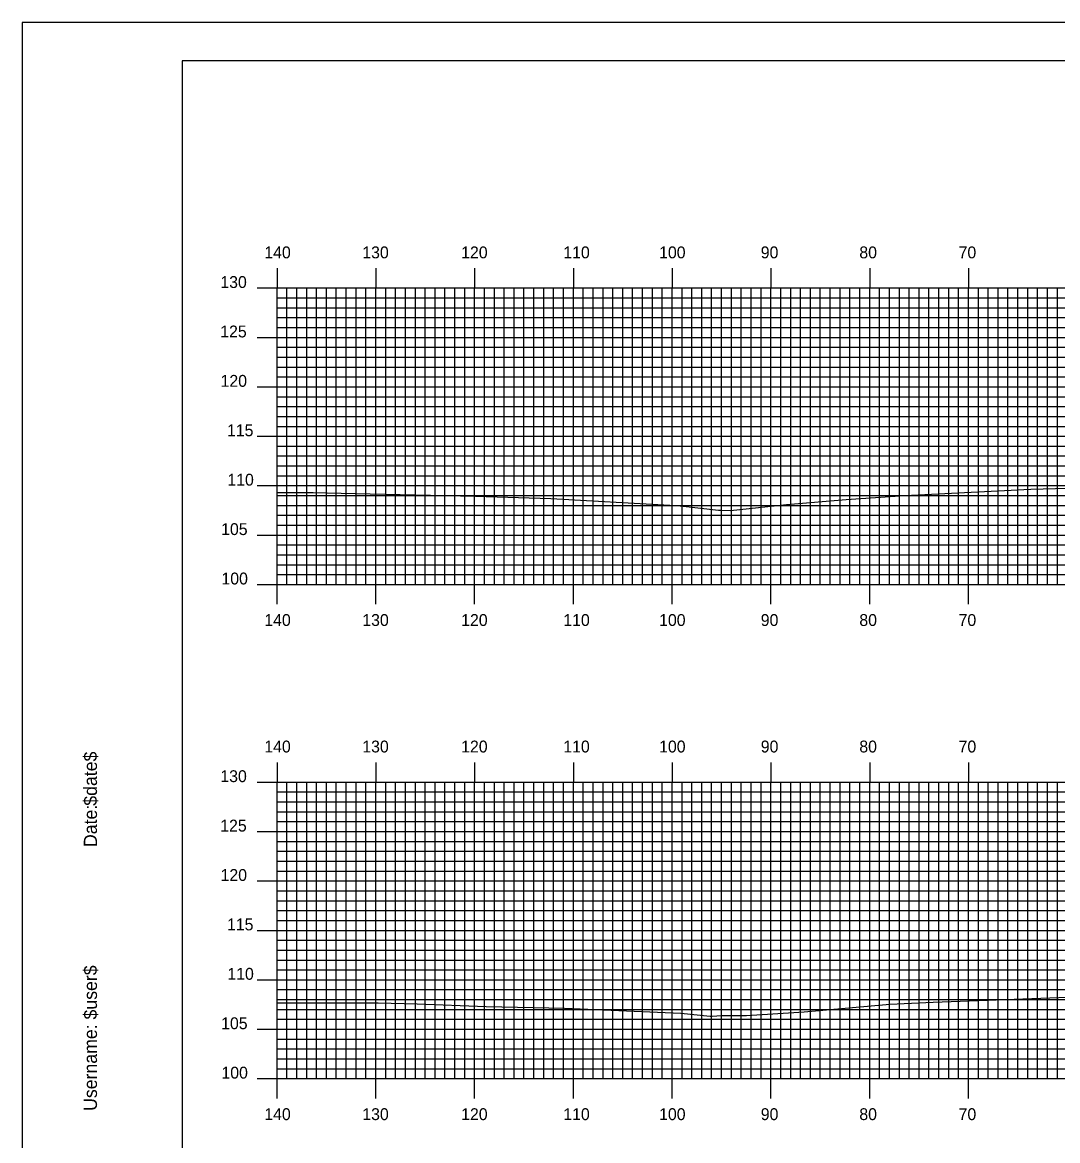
# Model space of a CAD drawing. Extents: x 1788156 to 1788500, y 442591 to 442811.
# Drawn here: x 1788156.3 to 1788261.2, y 442697.4 to 442810.5 of the extents above; entities that cross this region are included whole.
import ezdxf

# ---------------------------------------------------------------- set-up
doc = ezdxf.new("R2010")
doc.units = 0
for name, color, linetype in [('BORDER', 7, 'Continuous'), ('H_V ANNOTATION', 7, 'Continuous'), ('MAJOR', 7, 'Continuous'), ('MINOR', 7, 'Continuous'), ('PLOT BOUNDARY', 7, 'Continuous'), ('S_Roadway_Centerline', 7, 'Continuous')]:
    doc.layers.add(name, color=color, linetype=linetype)

msp = doc.modelspace()

# ---------------------------------------------------------------- linework, layer by layer
at = {"layer": 'BORDER'}
msp.add_lwpolyline([(1788172.53, 442596.67), (1788492.53, 442596.67), (1788492.53, 442806.67), (1788172.53, 442806.67)], close=True, dxfattribs=at)
at = {"layer": 'MAJOR'}
for p, q in [((1788182.13, 442785.67), (1788182.13, 442783.67)), ((1788192.13, 442785.67), (1788192.13, 442783.67)), ((1788202.13, 442785.67), (1788202.13, 442783.67)), ((1788212.13, 442785.67), (1788212.13, 442783.67)), ((1788222.13, 442785.67), (1788222.13, 442783.67)), ((1788232.13, 442785.67), (1788232.13, 442783.67)), ((1788242.13, 442785.67), (1788242.13, 442783.67)), ((1788252.13, 442785.67), (1788252.13, 442783.67)), ((1788180.13, 442783.67), (1788182.13, 442783.67)), ((1788182.13, 442783.67), (1788462.13, 442783.67)), ((1788182.13, 442753.67), (1788182.13, 442783.67)), ((1788182.13, 442753.67), (1788182.13, 442783.67)), ((1788182.13, 442783.67), (1788462.13, 442783.67)), ((1788192.13, 442753.67), (1788192.13, 442783.67)), ((1788202.13, 442753.67), (1788202.13, 442783.67)), ((1788212.13, 442753.67), (1788212.13, 442783.67)), ((1788222.13, 442753.67), (1788222.13, 442783.67)), ((1788232.13, 442753.67), (1788232.13, 442783.67)), ((1788242.13, 442753.67), (1788242.13, 442783.67)), ((1788252.13, 442753.67), (1788252.13, 442783.67)), ((1788180.13, 442778.67), (1788182.13, 442778.67)), ((1788182.13, 442778.67), (1788462.13, 442778.67)), ((1788180.13, 442773.67), (1788182.13, 442773.67)), ((1788182.13, 442773.67), (1788462.13, 442773.67)), ((1788180.13, 442768.67), (1788182.13, 442768.67)), ((1788182.13, 442768.67), (1788462.13, 442768.67)), ((1788180.13, 442763.67), (1788182.13, 442763.67)), ((1788182.13, 442763.67), (1788462.13, 442763.67)), ((1788180.13, 442758.67), (1788182.13, 442758.67)), ((1788182.13, 442758.67), (1788462.13, 442758.67)), ((1788180.13, 442753.67), (1788182.13, 442753.67)), ((1788182.13, 442753.67), (1788462.13, 442753.67)), ((1788182.13, 442753.67), (1788462.13, 442753.67)), ((1788182.13, 442751.66), (1788182.13, 442753.67)), ((1788192.13, 442751.66), (1788192.13, 442753.67)), ((1788202.13, 442751.66), (1788202.13, 442753.67)), ((1788212.13, 442751.66), (1788212.13, 442753.67)), ((1788222.13, 442751.66), (1788222.13, 442753.67)), ((1788232.13, 442751.66), (1788232.13, 442753.67)), ((1788242.13, 442751.66), (1788242.13, 442753.67)), ((1788252.13, 442751.66), (1788252.13, 442753.67)), ((1788182.13, 442735.67), (1788182.13, 442733.67)), ((1788192.13, 442735.67), (1788192.13, 442733.67)), ((1788202.13, 442735.67), (1788202.13, 442733.67)), ((1788212.13, 442735.67), (1788212.13, 442733.67)), ((1788222.13, 442735.67), (1788222.13, 442733.67)), ((1788232.13, 442735.67), (1788232.13, 442733.67)), ((1788242.13, 442735.67), (1788242.13, 442733.67)), ((1788252.13, 442735.67), (1788252.13, 442733.67)), ((1788180.13, 442733.67), (1788182.13, 442733.67)), ((1788182.13, 442733.67), (1788462.13, 442733.67)), ((1788182.13, 442703.67), (1788182.13, 442733.67)), ((1788182.13, 442703.67), (1788182.13, 442733.67)), ((1788182.13, 442733.67), (1788462.13, 442733.67)), ((1788192.13, 442703.67), (1788192.13, 442733.67)), ((1788202.13, 442703.67), (1788202.13, 442733.67)), ((1788212.13, 442703.67), (1788212.13, 442733.67)), ((1788222.13, 442703.67), (1788222.13, 442733.67)), ((1788232.13, 442703.67), (1788232.13, 442733.67)), ((1788242.13, 442703.67), (1788242.13, 442733.67)), ((1788252.13, 442703.67), (1788252.13, 442733.67)), ((1788180.13, 442728.67), (1788182.13, 442728.67)), ((1788182.13, 442728.67), (1788462.13, 442728.67)), ((1788180.13, 442723.67), (1788182.13, 442723.67)), ((1788182.13, 442723.67), (1788462.13, 442723.67)), ((1788180.13, 442718.67), (1788182.13, 442718.67)), ((1788182.13, 442718.67), (1788462.13, 442718.67)), ((1788180.13, 442713.67), (1788182.13, 442713.67)), ((1788182.13, 442713.67), (1788462.13, 442713.67)), ((1788180.13, 442708.67), (1788182.13, 442708.67)), ((1788182.13, 442708.67), (1788462.13, 442708.67)), ((1788180.13, 442703.67), (1788182.13, 442703.67)), ((1788182.13, 442703.67), (1788462.13, 442703.67)), ((1788182.13, 442703.67), (1788462.13, 442703.67)), ((1788182.13, 442701.66), (1788182.13, 442703.67)), ((1788192.13, 442701.66), (1788192.13, 442703.67)), ((1788202.13, 442701.66), (1788202.13, 442703.67)), ((1788212.13, 442701.66), (1788212.13, 442703.67)), ((1788222.13, 442701.66), (1788222.13, 442703.67)), ((1788232.13, 442701.66), (1788232.13, 442703.67)), ((1788242.13, 442701.66), (1788242.13, 442703.67)), ((1788252.13, 442701.66), (1788252.13, 442703.67))]:
    msp.add_line(p, q, dxfattribs=at)
at = {"layer": 'MINOR'}
for p, q in [((1788183.13, 442753.67), (1788183.13, 442783.67)), ((1788184.13, 442753.67), (1788184.13, 442783.67)), ((1788185.13, 442753.67), (1788185.13, 442783.67)), ((1788186.13, 442753.67), (1788186.13, 442783.67)), ((1788187.13, 442753.67), (1788187.13, 442783.67)), ((1788188.13, 442753.67), (1788188.13, 442783.67)), ((1788189.13, 442753.67), (1788189.13, 442783.67)), ((1788190.13, 442753.67), (1788190.13, 442783.67)), ((1788191.13, 442753.67), (1788191.13, 442783.67)), ((1788193.13, 442753.67), (1788193.13, 442783.67)), ((1788194.13, 442753.67), (1788194.13, 442783.67)), ((1788195.13, 442753.67), (1788195.13, 442783.67)), ((1788196.13, 442753.67), (1788196.13, 442783.67)), ((1788197.13, 442753.67), (1788197.13, 442783.67)), ((1788198.13, 442753.67), (1788198.13, 442783.67)), ((1788199.13, 442753.67), (1788199.13, 442783.67)), ((1788200.13, 442753.67), (1788200.13, 442783.67)), ((1788201.13, 442753.67), (1788201.13, 442783.67)), ((1788203.13, 442753.67), (1788203.13, 442783.67)), ((1788204.13, 442753.67), (1788204.13, 442783.67)), ((1788205.13, 442753.67), (1788205.13, 442783.67)), ((1788206.13, 442753.67), (1788206.13, 442783.67)), ((1788207.13, 442753.67), (1788207.13, 442783.67)), ((1788208.13, 442753.67), (1788208.13, 442783.67)), ((1788209.13, 442753.67), (1788209.13, 442783.67)), ((1788210.13, 442753.67), (1788210.13, 442783.67)), ((1788211.13, 442753.67), (1788211.13, 442783.67)), ((1788213.13, 442753.67), (1788213.13, 442783.67)), ((1788214.13, 442753.67), (1788214.13, 442783.67)), ((1788215.13, 442753.67), (1788215.13, 442783.67)), ((1788216.13, 442753.67), (1788216.13, 442783.67)), ((1788217.13, 442753.67), (1788217.13, 442783.67)), ((1788218.13, 442753.67), (1788218.13, 442783.67)), ((1788219.13, 442753.67), (1788219.13, 442783.67)), ((1788220.13, 442753.67), (1788220.13, 442783.67)), ((1788221.13, 442753.67), (1788221.13, 442783.67)), ((1788223.13, 442753.67), (1788223.13, 442783.67)), ((1788224.13, 442753.67), (1788224.13, 442783.67)), ((1788225.13, 442753.67), (1788225.13, 442783.67)), ((1788226.13, 442753.67), (1788226.13, 442783.67)), ((1788227.13, 442753.67), (1788227.13, 442783.67)), ((1788228.13, 442753.67), (1788228.13, 442783.67)), ((1788229.13, 442753.67), (1788229.13, 442783.67)), ((1788230.13, 442753.67), (1788230.13, 442783.67)), ((1788231.13, 442753.67), (1788231.13, 442783.67)), ((1788233.13, 442753.67), (1788233.13, 442783.67)), ((1788234.13, 442753.67), (1788234.13, 442783.67)), ((1788235.13, 442753.67), (1788235.13, 442783.67)), ((1788236.13, 442753.67), (1788236.13, 442783.67)), ((1788237.13, 442753.67), (1788237.13, 442783.67)), ((1788238.13, 442753.67), (1788238.13, 442783.67)), ((1788239.13, 442753.67), (1788239.13, 442783.67)), ((1788240.13, 442753.67), (1788240.13, 442783.67)), ((1788241.13, 442753.67), (1788241.13, 442783.67)), ((1788243.13, 442753.67), (1788243.13, 442783.67)), ((1788244.13, 442753.67), (1788244.13, 442783.67)), ((1788245.13, 442753.67), (1788245.13, 442783.67)), ((1788246.13, 442753.67), (1788246.13, 442783.67)), ((1788247.13, 442753.67), (1788247.13, 442783.67)), ((1788248.13, 442753.67), (1788248.13, 442783.67)), ((1788249.13, 442753.67), (1788249.13, 442783.67)), ((1788250.13, 442753.67), (1788250.13, 442783.67)), ((1788251.13, 442753.67), (1788251.13, 442783.67)), ((1788253.13, 442753.67), (1788253.13, 442783.67)), ((1788254.13, 442753.67), (1788254.13, 442783.67)), ((1788255.13, 442753.67), (1788255.13, 442783.67)), ((1788256.13, 442753.67), (1788256.13, 442783.67)), ((1788257.13, 442753.67), (1788257.13, 442783.67)), ((1788258.13, 442753.67), (1788258.13, 442783.67)), ((1788259.13, 442753.67), (1788259.13, 442783.67)), ((1788260.13, 442753.67), (1788260.13, 442783.67)), ((1788261.13, 442753.67), (1788261.13, 442783.67)), ((1788182.13, 442782.67), (1788462.13, 442782.67)), ((1788182.13, 442782.67), (1788184.13, 442782.67)), ((1788182.13, 442781.67), (1788462.13, 442781.67)), ((1788182.13, 442781.67), (1788184.13, 442781.67)), ((1788182.13, 442780.67), (1788462.13, 442780.67)), ((1788182.13, 442780.67), (1788184.13, 442780.67)), ((1788182.13, 442779.67), (1788462.13, 442779.67)), ((1788182.13, 442779.67), (1788184.13, 442779.67)), ((1788182.13, 442777.67), (1788462.13, 442777.67)), ((1788182.13, 442777.67), (1788184.13, 442777.67)), ((1788182.13, 442776.67), (1788462.13, 442776.67)), ((1788182.13, 442776.67), (1788184.13, 442776.67)), ((1788182.13, 442775.67), (1788462.13, 442775.67)), ((1788182.13, 442775.67), (1788184.13, 442775.67)), ((1788182.13, 442774.67), (1788462.13, 442774.67)), ((1788182.13, 442774.67), (1788184.13, 442774.67)), ((1788182.13, 442772.67), (1788462.13, 442772.67)), ((1788182.13, 442772.67), (1788184.13, 442772.67)), ((1788182.13, 442771.67), (1788462.13, 442771.67)), ((1788182.13, 442771.67), (1788184.13, 442771.67)), ((1788182.13, 442770.67), (1788462.13, 442770.67)), ((1788182.13, 442770.67), (1788184.13, 442770.67)), ((1788182.13, 442769.67), (1788462.13, 442769.67)), ((1788182.13, 442769.67), (1788184.13, 442769.67)), ((1788182.13, 442767.67), (1788462.13, 442767.67)), ((1788182.13, 442767.67), (1788184.13, 442767.67)), ((1788182.13, 442766.67), (1788462.13, 442766.67)), ((1788182.13, 442766.67), (1788184.13, 442766.67)), ((1788182.13, 442765.67), (1788462.13, 442765.67)), ((1788182.13, 442765.67), (1788184.13, 442765.67)), ((1788182.13, 442764.67), (1788462.13, 442764.67)), ((1788182.13, 442764.67), (1788184.13, 442764.67)), ((1788182.13, 442762.67), (1788462.13, 442762.67)), ((1788182.13, 442762.67), (1788184.13, 442762.67)), ((1788182.13, 442761.67), (1788462.13, 442761.67)), ((1788182.13, 442761.67), (1788184.13, 442761.67)), ((1788182.13, 442760.67), (1788462.13, 442760.67)), ((1788182.13, 442760.67), (1788184.13, 442760.67)), ((1788182.13, 442759.67), (1788462.13, 442759.67)), ((1788182.13, 442759.67), (1788184.13, 442759.67)), ((1788182.13, 442757.67), (1788462.13, 442757.67)), ((1788182.13, 442757.67), (1788184.13, 442757.67)), ((1788182.13, 442756.67), (1788462.13, 442756.67)), ((1788182.13, 442756.67), (1788184.13, 442756.67)), ((1788182.13, 442755.67), (1788462.13, 442755.67)), ((1788182.13, 442755.67), (1788184.13, 442755.67)), ((1788182.13, 442754.67), (1788462.13, 442754.67)), ((1788182.13, 442754.67), (1788184.13, 442754.67)), ((1788183.13, 442703.67), (1788183.13, 442733.67)), ((1788184.13, 442703.67), (1788184.13, 442733.67)), ((1788185.13, 442703.67), (1788185.13, 442733.67)), ((1788186.13, 442703.67), (1788186.13, 442733.67)), ((1788187.13, 442703.67), (1788187.13, 442733.67)), ((1788188.13, 442703.67), (1788188.13, 442733.67)), ((1788189.13, 442703.67), (1788189.13, 442733.67)), ((1788190.13, 442703.67), (1788190.13, 442733.67)), ((1788191.13, 442703.67), (1788191.13, 442733.67)), ((1788193.13, 442703.67), (1788193.13, 442733.67)), ((1788194.13, 442703.67), (1788194.13, 442733.67)), ((1788195.13, 442703.67), (1788195.13, 442733.67)), ((1788196.13, 442703.67), (1788196.13, 442733.67)), ((1788197.13, 442703.67), (1788197.13, 442733.67)), ((1788198.13, 442703.67), (1788198.13, 442733.67)), ((1788199.13, 442703.67), (1788199.13, 442733.67)), ((1788200.13, 442703.67), (1788200.13, 442733.67)), ((1788201.13, 442703.67), (1788201.13, 442733.67)), ((1788203.13, 442703.67), (1788203.13, 442733.67)), ((1788204.13, 442703.67), (1788204.13, 442733.67)), ((1788205.13, 442703.67), (1788205.13, 442733.67)), ((1788206.13, 442703.67), (1788206.13, 442733.67)), ((1788207.13, 442703.67), (1788207.13, 442733.67)), ((1788208.13, 442703.67), (1788208.13, 442733.67)), ((1788209.13, 442703.67), (1788209.13, 442733.67)), ((1788210.13, 442703.67), (1788210.13, 442733.67)), ((1788211.13, 442703.67), (1788211.13, 442733.67)), ((1788213.13, 442703.67), (1788213.13, 442733.67)), ((1788214.13, 442703.67), (1788214.13, 442733.67)), ((1788215.13, 442703.67), (1788215.13, 442733.67)), ((1788216.13, 442703.67), (1788216.13, 442733.67)), ((1788217.13, 442703.67), (1788217.13, 442733.67)), ((1788218.13, 442703.67), (1788218.13, 442733.67)), ((1788219.13, 442703.67), (1788219.13, 442733.67)), ((1788220.13, 442703.67), (1788220.13, 442733.67)), ((1788221.13, 442703.67), (1788221.13, 442733.67)), ((1788223.13, 442703.67), (1788223.13, 442733.67)), ((1788224.13, 442703.67), (1788224.13, 442733.67)), ((1788225.13, 442703.67), (1788225.13, 442733.67)), ((1788226.13, 442703.67), (1788226.13, 442733.67)), ((1788227.13, 442703.67), (1788227.13, 442733.67)), ((1788228.13, 442703.67), (1788228.13, 442733.67)), ((1788229.13, 442703.67), (1788229.13, 442733.67)), ((1788230.13, 442703.67), (1788230.13, 442733.67)), ((1788231.13, 442703.67), (1788231.13, 442733.67)), ((1788233.13, 442703.67), (1788233.13, 442733.67)), ((1788234.13, 442703.67), (1788234.13, 442733.67)), ((1788235.13, 442703.67), (1788235.13, 442733.67)), ((1788236.13, 442703.67), (1788236.13, 442733.67)), ((1788237.13, 442703.67), (1788237.13, 442733.67)), ((1788238.13, 442703.67), (1788238.13, 442733.67)), ((1788239.13, 442703.67), (1788239.13, 442733.67)), ((1788240.13, 442703.67), (1788240.13, 442733.67)), ((1788241.13, 442703.67), (1788241.13, 442733.67)), ((1788243.13, 442703.67), (1788243.13, 442733.67)), ((1788244.13, 442703.67), (1788244.13, 442733.67)), ((1788245.13, 442703.67), (1788245.13, 442733.67)), ((1788246.13, 442703.67), (1788246.13, 442733.67)), ((1788247.13, 442703.67), (1788247.13, 442733.67)), ((1788248.13, 442703.67), (1788248.13, 442733.67)), ((1788249.13, 442703.67), (1788249.13, 442733.67)), ((1788250.13, 442703.67), (1788250.13, 442733.67)), ((1788251.13, 442703.67), (1788251.13, 442733.67)), ((1788253.13, 442703.67), (1788253.13, 442733.67)), ((1788254.13, 442703.67), (1788254.13, 442733.67)), ((1788255.13, 442703.67), (1788255.13, 442733.67)), ((1788256.13, 442703.67), (1788256.13, 442733.67)), ((1788257.13, 442703.67), (1788257.13, 442733.67)), ((1788258.13, 442703.67), (1788258.13, 442733.67)), ((1788259.13, 442703.67), (1788259.13, 442733.67)), ((1788260.13, 442703.67), (1788260.13, 442733.67)), ((1788261.13, 442703.67), (1788261.13, 442733.67)), ((1788182.13, 442732.67), (1788462.13, 442732.67)), ((1788182.13, 442732.67), (1788184.13, 442732.67)), ((1788182.13, 442731.67), (1788462.13, 442731.67)), ((1788182.13, 442731.67), (1788184.13, 442731.67)), ((1788182.13, 442730.67), (1788462.13, 442730.67)), ((1788182.13, 442730.67), (1788184.13, 442730.67)), ((1788182.13, 442729.67), (1788462.13, 442729.67)), ((1788182.13, 442729.67), (1788184.13, 442729.67)), ((1788182.13, 442727.67), (1788462.13, 442727.67)), ((1788182.13, 442727.67), (1788184.13, 442727.67)), ((1788182.13, 442726.67), (1788462.13, 442726.67)), ((1788182.13, 442726.67), (1788184.13, 442726.67)), ((1788182.13, 442725.67), (1788462.13, 442725.67)), ((1788182.13, 442725.67), (1788184.13, 442725.67)), ((1788182.13, 442724.67), (1788462.13, 442724.67)), ((1788182.13, 442724.67), (1788184.13, 442724.67)), ((1788182.13, 442722.67), (1788462.13, 442722.67)), ((1788182.13, 442722.67), (1788184.13, 442722.67)), ((1788182.13, 442721.67), (1788462.13, 442721.67)), ((1788182.13, 442721.67), (1788184.13, 442721.67)), ((1788182.13, 442720.67), (1788462.13, 442720.67)), ((1788182.13, 442720.67), (1788184.13, 442720.67)), ((1788182.13, 442719.67), (1788462.13, 442719.67)), ((1788182.13, 442719.67), (1788184.13, 442719.67)), ((1788182.13, 442717.67), (1788462.13, 442717.67)), ((1788182.13, 442717.67), (1788184.13, 442717.67)), ((1788182.13, 442716.67), (1788462.13, 442716.67)), ((1788182.13, 442716.67), (1788184.13, 442716.67)), ((1788182.13, 442715.67), (1788462.13, 442715.67)), ((1788182.13, 442715.67), (1788184.13, 442715.67)), ((1788182.13, 442714.67), (1788462.13, 442714.67)), ((1788182.13, 442714.67), (1788184.13, 442714.67)), ((1788182.13, 442712.67), (1788462.13, 442712.67)), ((1788182.13, 442712.67), (1788184.13, 442712.67)), ((1788182.13, 442711.67), (1788462.13, 442711.67)), ((1788182.13, 442711.67), (1788184.13, 442711.67)), ((1788182.13, 442710.67), (1788462.13, 442710.67)), ((1788182.13, 442710.67), (1788184.13, 442710.67)), ((1788182.13, 442709.67), (1788462.13, 442709.67)), ((1788182.13, 442709.67), (1788184.13, 442709.67)), ((1788182.13, 442707.67), (1788462.13, 442707.67)), ((1788182.13, 442707.67), (1788184.13, 442707.67)), ((1788182.13, 442706.67), (1788462.13, 442706.67)), ((1788182.13, 442706.67), (1788184.13, 442706.67)), ((1788182.13, 442705.67), (1788462.13, 442705.67)), ((1788182.13, 442705.67), (1788184.13, 442705.67)), ((1788182.13, 442704.67), (1788462.13, 442704.67)), ((1788182.13, 442704.67), (1788184.13, 442704.67))]:
    msp.add_line(p, q, dxfattribs=at)
at = {"layer": 'PLOT BOUNDARY'}
msp.add_lwpolyline([(1788156.34, 442590.55), (1788496.34, 442590.55), (1788496.34, 442810.55), (1788156.34, 442810.55)], close=True, dxfattribs=at)
at = {"layer": 'S_Roadway_Centerline'}
for points in [[(1788182.13, 442762.97), (1788183.41, 442762.99), (1788185.78, 442762.97), (1788190.03, 442762.87), (1788202.22, 442762.6), (1788209.84, 442762.38), (1788221.91, 442761.7), (1788222.94, 442761.62), (1788226.82, 442761.2), (1788227.08, 442761.19), (1788228.02, 442761.17), (1788233.72, 442761.76), (1788239.76, 442762.26), (1788245.68, 442762.66), (1788256.45, 442763.21), (1788257.74, 442763.29), (1788258.44, 442763.31), (1788269.72, 442763.6)], [(1788182.13, 442711.33), (1788184.38, 442711.35), (1788192.36, 442711.35), (1788196.33, 442711.24), (1788203.3, 442710.98), (1788211.22, 442710.81), (1788223.01, 442710.28), (1788225.98, 442709.97), (1788226.19, 442709.99), (1788227.13, 442710.06), (1788229.65, 442710.05), (1788235.5, 442710.43), (1788244.17, 442711.19), (1788248.55, 442711.4), (1788265.85, 442712.05)]]:
    msp.add_lwpolyline(points, dxfattribs=at)

# ---------------------------------------------------------------- texts
at = {"layer": 'BORDER'}
for s, p in [('$date$', (1788163.9, 442731.28)), ('Date:', (1788163.9, 442727.1)), ('$user$', (1788163.9, 442709.65)), ('Username:', (1788163.9, 442700.4))]:
    msp.add_text(s, height=1.339, rotation=90, dxfattribs=at).set_placement(p)
at = {"layer": 'H_V ANNOTATION'}
for s, p in [('140', (1788180.84, 442786.67)), ('130', (1788190.76, 442786.67)), ('120', (1788200.77, 442786.67)), ('110', (1788211.11, 442786.67)), ('100', (1788220.81, 442786.67)), ('90', (1788231.1, 442786.67)), ('80', (1788241.08, 442786.67)), ('70', (1788251.13, 442786.67)), ('130', (1788176.39, 442783.67)), ('125', (1788176.38, 442778.67)), ('120', (1788176.41, 442773.67)), ('115', (1788177.06, 442768.67)), ('110', (1788177.1, 442763.67)), ('105', (1788176.47, 442758.67)), ('100', (1788176.5, 442753.67)), ('140', (1788180.84, 442749.47)), ('130', (1788190.76, 442749.47)), ('120', (1788200.77, 442749.47)), ('110', (1788211.11, 442749.47)), ('100', (1788220.81, 442749.47)), ('90', (1788231.1, 442749.47)), ('80', (1788241.08, 442749.47)), ('70', (1788251.13, 442749.47)), ('140', (1788180.84, 442736.67)), ('130', (1788190.76, 442736.67)), ('120', (1788200.77, 442736.67)), ('110', (1788211.11, 442736.67)), ('100', (1788220.81, 442736.67)), ('90', (1788231.1, 442736.67)), ('80', (1788241.08, 442736.67)), ('70', (1788251.13, 442736.67)), ('130', (1788176.39, 442733.67)), ('125', (1788176.38, 442728.67)), ('120', (1788176.41, 442723.67)), ('115', (1788177.06, 442718.67)), ('110', (1788177.1, 442713.67)), ('105', (1788176.47, 442708.67)), ('100', (1788176.5, 442703.67)), ('140', (1788180.84, 442699.47)), ('130', (1788190.76, 442699.47)), ('120', (1788200.77, 442699.47)), ('110', (1788211.11, 442699.47)), ('100', (1788220.81, 442699.47)), ('90', (1788231.1, 442699.47)), ('80', (1788241.08, 442699.47)), ('70', (1788251.13, 442699.47))]:
    msp.add_text(s, height=1.2, dxfattribs=at).set_placement(p)
at = {"layer": 'MAJOR'}
for p in [(1788182.12, 442753.67), (1788182.12, 442703.67)]:
    msp.add_text('-', height=0.012, dxfattribs=at).set_placement(p)

doc.saveas('drawing.dxf')
